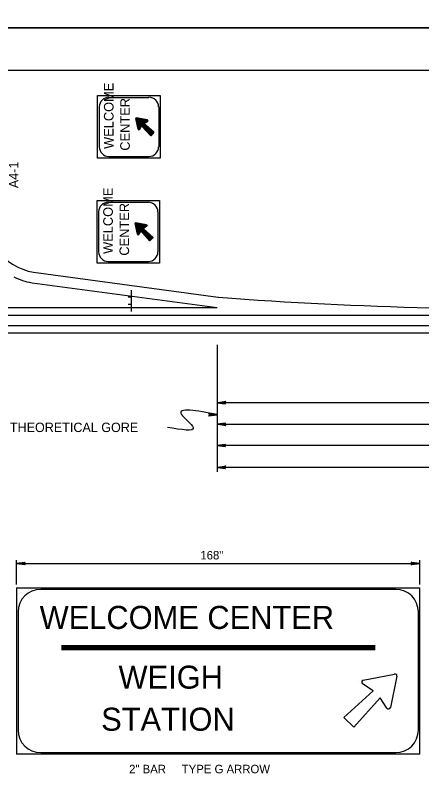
# Model space of a CAD drawing. Extents: x 2189973 to 2192941, y 2147557 to 2151454.
# Drawn here: x 2190705 to 2191176, y 2148636 to 2149520 of the extents above; entities that cross this region are included whole.
import ezdxf

# ---------------------------------------------------------------- set-up
doc = ezdxf.new("R2010")
doc.units = 0
doc.layers.add('Default', color=7, linetype='Continuous')
doc.layers.add('PLT-BNDY', color=7, linetype='Continuous')

# ---------------------------------------------------------------- blocks, each defined once
blk = doc.blocks.new('RARROW')
at = {"layer": 'Default'}
blk.add_lwpolyline([(-18.156, 2.28), (-17.479, 0.966), (0, 0), (-18.156, 2.28), (-19.086, 3.077), (0, 0), (-17.465, -0.864), (-18.103, -2.164), (0, 0), (-19.086, -3.033), (-18.103, -2.164)], dxfattribs=at)

msp = doc.modelspace()

# ---------------------------------------------------------------- linework, layer by layer
at = {"layer": 'Default'}
for p, q in [((2190104.48, 2149456.38), (2192683.21, 2149456.38)), ((2190813.55, 2149424.8), (2190859.89, 2149424.8)), ((2190844.31, 2149401.02), (2190844.31, 2149401.02)), ((2190844.72, 2149400.2), (2190847.59, 2149387.9)), ((2190857.84, 2149398.56), (2190845.54, 2149401.02)), ((2190854.15, 2149394.46), (2190858.66, 2149397.33)), ((2190859.89, 2149398.15), (2190859.89, 2149398.15)), ((2190848, 2149386.25), (2190848, 2149386.25)), ((2190848.82, 2149387.49), (2190851.28, 2149391.59)), ((2190851.28, 2149391.59), (2190851.28, 2149391.59)), ((2190851.28, 2149391.59), (2190861.94, 2149380.1)), ((2190854.15, 2149394.46), (2190854.15, 2149394.46)), ((2190865.63, 2149384.2), (2190854.15, 2149394.46)), ((2190861.94, 2149380.1), (2190865.63, 2149384.2)), ((2190873.02, 2149354.27), (2190800.43, 2149354.27)), ((2190859.89, 2149355.91), (2190813.55, 2149355.91)), ((2190812.73, 2149303), (2190859.48, 2149303)), ((2190843.49, 2149279.22), (2190843.49, 2149279.22)), ((2190843.9, 2149278.4), (2190846.77, 2149266.09)), ((2190857.02, 2149276.76), (2190844.72, 2149279.22)), ((2190853.33, 2149272.66), (2190857.43, 2149275.53)), ((2190853.33, 2149272.66), (2190853.33, 2149272.66)), ((2190864.81, 2149261.99), (2190853.33, 2149272.66)), ((2190859.07, 2149276.35), (2190859.07, 2149276.35)), ((2190847.18, 2149264.45), (2190847.18, 2149264.45)), ((2190848, 2149265.68), (2190850.46, 2149269.79)), ((2190850.46, 2149269.79), (2190850.46, 2149269.79)), ((2190850.46, 2149269.79), (2190861.12, 2149258.3)), ((2190861.12, 2149258.3), (2190864.81, 2149261.99)), ((2190872.19, 2149232.47), (2190800.02, 2149232.47)), ((2190859.48, 2149234.11), (2190812.73, 2149234.11)), ((2190726.2, 2149221.8), (2190940.27, 2149193.1)), ((2190724.56, 2149209.5), (2190724.56, 2149209.5)), ((2190724.56, 2149209.5), (2190939.04, 2149180.79)), ((2190839.8, 2149176.28), (2190839.8, 2149200.89)), ((2190839.8, 2149193.1), (2190835.7, 2149193.1)), ((2190839.8, 2149184.48), (2190835.7, 2149184.48)), ((2190155.33, 2149180.79), (2190939.04, 2149180.79)), ((2190939.04, 2149180.79), (2190939.04, 2149180.79)), ((2190939.04, 2149180.79), (2190939.04, 2149180.79)), ((2190114.32, 2149172.18), (2192679.93, 2149172.18)), ((2190114.32, 2149159.88), (2192679.93, 2149159.88)), ((2190114.32, 2149151.68), (2192679.93, 2149151.68)), ((2190939.04, 2149137.73), (2190939.04, 2148990.09)), ((2191714.55, 2149070.47), (2190939.04, 2149070.47)), ((2190939.04, 2149045.46), (2192091.43, 2149045.46)), ((2192264.5, 2149020.85), (2190939.04, 2149020.85)), ((2192437.97, 2148995.43), (2190939.04, 2148995.43)), ((2190706.54, 2148859.67), (2190706.54, 2148887.96)), ((2190706.54, 2148883.86), (2191174.05, 2148883.86)), ((2191174.05, 2148859.67), (2191174.05, 2148887.96)), ((2190706.54, 2148855.56), (2191174.05, 2148855.56)), ((2190706.54, 2148855.56), (2190706.54, 2148662.82)), ((2191146.17, 2148853.92), (2190734.42, 2148853.92)), ((2191174.05, 2148662.82), (2191174.05, 2148855.56)), ((2190708.18, 2148827.68), (2190708.18, 2148690.7)), ((2191172.41, 2148690.7), (2191172.41, 2148827.68)), ((2190758.62, 2148788.72), (2191122.38, 2148788.72)), ((2190758.62, 2148787.9), (2191122.38, 2148787.9)), ((2190758.62, 2148786.67), (2191122.38, 2148786.67)), ((2190758.62, 2148785.85), (2191122.38, 2148785.85)), ((2190758.62, 2148785.03), (2191122.38, 2148785.03)), ((2190758.62, 2148784.21), (2191122.38, 2148784.21)), ((2191108.44, 2148748.53), (2191144.53, 2148755.5)), ((2191147.4, 2148753.04), (2191140.02, 2148716.95)), ((2191147.4, 2148753.04), (2191140.02, 2148716.95)), ((2191147.81, 2148756.32), (2191147.81, 2148756.32)), ((2191103.52, 2148747.3), (2191103.52, 2148747.3)), ((2191119.92, 2148736.22), (2191107.62, 2148744.43)), ((2191119.92, 2148736.22), (2191107.62, 2148744.43)), ((2191085.88, 2148705.06), (2191119.92, 2148736.22)), ((2191085.88, 2148705.06), (2191119.92, 2148736.22)), ((2191119.92, 2148736.22), (2191119.92, 2148736.22)), ((2191128.12, 2148728.02), (2191097.36, 2148693.98)), ((2191128.12, 2148728.02), (2191097.36, 2148693.98)), ((2191124.02, 2148732.12), (2191124.02, 2148732.12)), ((2191135.91, 2148716.13), (2191128.12, 2148728.02)), ((2191128.12, 2148728.02), (2191128.12, 2148728.02)), ((2191139.2, 2148712.03), (2191139.2, 2148712.03)), ((2191097.36, 2148693.98), (2191085.88, 2148705.06)), ((2191097.36, 2148693.98), (2191085.88, 2148705.06)), ((2191085.88, 2148705.06), (2191085.88, 2148705.06)), ((2191097.36, 2148693.98), (2191097.36, 2148693.98)), ((2191174.05, 2148662.82), (2190706.54, 2148662.82)), ((2190734.42, 2148664.46), (2191146.17, 2148664.46))]:
    msp.add_line(p, q, dxfattribs=at)
for points in [[(2190800.43, 2149354.27), (2190800.43, 2149426.86), (2190807.81, 2149426.86), (2190818.88, 2149426.86), (2190826.67, 2149426.86), (2190837.75, 2149426.86), (2190844.31, 2149426.86), (2190866.04, 2149426.86), (2190873.02, 2149426.86), (2190873.02, 2149426.86), (2190873.02, 2149354.27), (2190873.02, 2149354.27)], [(2190802.48, 2149367.39), (2190802.48, 2149413.73)], [(2190871.37, 2149413.73), (2190871.37, 2149367.39)], [(2190861.94, 2149380.1), (2190851.28, 2149391.59), (2190848.82, 2149387.49), (2190848, 2149387.49), (2190847.59, 2149387.9), (2190844.72, 2149400.2), (2190845.13, 2149400.61), (2190845.54, 2149401.02), (2190857.84, 2149398.15), (2190858.66, 2149397.74), (2190857.84, 2149397.33), (2190853.74, 2149394.46), (2190865.63, 2149384.2), (2190861.94, 2149380.1), (2190851.28, 2149392), (2190848.41, 2149387.49), (2190848, 2149387.49), (2190848, 2149387.9), (2190845.13, 2149400.2), (2190845.13, 2149400.61), (2190845.54, 2149400.61), (2190857.84, 2149398.15), (2190857.84, 2149397.74), (2190857.84, 2149397.33), (2190853.74, 2149394.46), (2190865.22, 2149384.2), (2190861.94, 2149380.51), (2190851.28, 2149392), (2190848.41, 2149387.9), (2190848, 2149387.9), (2190848, 2149387.9), (2190845.13, 2149400.61), (2190857.84, 2149397.74), (2190853.33, 2149394.46), (2190864.81, 2149383.79), (2190861.94, 2149380.92), (2190851.28, 2149392.41), (2190848, 2149387.9), (2190845.54, 2149400.2)], [(2190848.41, 2149388.31), (2190845.54, 2149400.61), (2190857.84, 2149397.74), (2190852.92, 2149394.46), (2190864.81, 2149383.79), (2190861.94, 2149380.92), (2190851.28, 2149392.41), (2190848.41, 2149388.72), (2190846.36, 2149400.2), (2190857.43, 2149397.74), (2190852.92, 2149394.46), (2190864.4, 2149383.79), (2190861.94, 2149381.33), (2190851.28, 2149392.82), (2190848.41, 2149389.13), (2190846.36, 2149399.79), (2190856.61, 2149397.33), (2190852.51, 2149394.46), (2190863.99, 2149383.79), (2190861.94, 2149382.15), (2190851.28, 2149392.82), (2190848.82, 2149389.95), (2190846.77, 2149399.38), (2190855.79, 2149397.33), (2190852.1, 2149394.46), (2190863.58, 2149384.2), (2190861.94, 2149382.15), (2190851.28, 2149393.23), (2190848.82, 2149390.77), (2190847.18, 2149398.97), (2190855.38, 2149397.33), (2190851.69, 2149394.46), (2190863.17, 2149384.2), (2190861.94, 2149382.56), (2190851.28, 2149393.64), (2190848.82, 2149391.18), (2190847.59, 2149398.56), (2190854.56, 2149396.92), (2190851.69, 2149394.46), (2190862.76, 2149384.2), (2190862.76, 2149384.2), (2190861.94, 2149383.38), (2190850.87, 2149393.64), (2190849.23, 2149391.59), (2190848, 2149398.56), (2190854.15, 2149396.92), (2190851.28, 2149394.46), (2190862.35, 2149383.79), (2190861.94, 2149383.79), (2190851.28, 2149394.05), (2190849.23, 2149392.41), (2190848, 2149398.15), (2190853.33, 2149396.92), (2190851.28, 2149394.46), (2190862.35, 2149383.79), (2190861.94, 2149383.79), (2190851.28, 2149394.46), (2190849.64, 2149392.82), (2190848.41, 2149397.74), (2190853.33, 2149396.51), (2190849.64, 2149393.23), (2190848.82, 2149397.33), (2190852.51, 2149396.51), (2190849.64, 2149393.64), (2190849.23, 2149396.92), (2190852.1, 2149396.51), (2190849.64, 2149394.05), (2190849.23, 2149396.92), (2190851.69, 2149396.1), (2190850.05, 2149394.87), (2190849.64, 2149396.51), (2190850.87, 2149396.1), (2190850.05, 2149395.69), (2190850.05, 2149396.1), (2190850.46, 2149396.1)], [(2190800.02, 2149232.47), (2190800.02, 2149305.05), (2190806.99, 2149305.05), (2190818.06, 2149305.05), (2190825.85, 2149305.05), (2190836.93, 2149305.05), (2190843.49, 2149305.05), (2190865.22, 2149305.05), (2190872.19, 2149305.05), (2190872.19, 2149305.05), (2190872.19, 2149232.47), (2190872.19, 2149232.47)], [(2190801.66, 2149245.59), (2190801.66, 2149291.93)], [(2190870.14, 2149291.93), (2190870.14, 2149245.59)], [(2190861.12, 2149258.3), (2190850.46, 2149269.79), (2190848, 2149265.68), (2190847.59, 2149265.68), (2190846.77, 2149266.09), (2190843.9, 2149278.4), (2190844.31, 2149278.81), (2190844.72, 2149279.22), (2190857.02, 2149276.35), (2190857.43, 2149275.94), (2190857.43, 2149275.53), (2190853.33, 2149272.66), (2190864.81, 2149261.99), (2190861.12, 2149258.3), (2190850.46, 2149270.2), (2190847.59, 2149265.68), (2190847.59, 2149265.68), (2190847.18, 2149266.09), (2190844.31, 2149278.4), (2190844.31, 2149278.81), (2190844.72, 2149278.81), (2190857.02, 2149276.35), (2190857.43, 2149275.94), (2190857.02, 2149275.53), (2190852.92, 2149272.66), (2190864.4, 2149261.99), (2190861.12, 2149258.71), (2190850.46, 2149270.2), (2190847.59, 2149266.09), (2190847.18, 2149266.09), (2190847.18, 2149266.09), (2190844.31, 2149278.81), (2190857.02, 2149275.94), (2190852.92, 2149272.66), (2190864.4, 2149261.58), (2190861.12, 2149259.12), (2190850.46, 2149270.2), (2190847.59, 2149266.09), (2190844.72, 2149278.4)], [(2190847.59, 2149266.5), (2190844.72, 2149278.81), (2190857.02, 2149275.94), (2190852.51, 2149272.66), (2190863.99, 2149261.58), (2190861.12, 2149259.12), (2190850.46, 2149270.61), (2190847.59, 2149266.91), (2190845.13, 2149278.4), (2190856.61, 2149275.94), (2190852.1, 2149272.66), (2190863.99, 2149261.58), (2190861.12, 2149259.53), (2190850.46, 2149271.02), (2190848, 2149267.32), (2190845.13, 2149277.99), (2190855.79, 2149275.53), (2190851.69, 2149272.66), (2190863.58, 2149261.58), (2190861.12, 2149259.94), (2190850.46, 2149271.02), (2190848, 2149268.14), (2190845.54, 2149277.58), (2190854.97, 2149275.53), (2190851.28, 2149272.66), (2190862.76, 2149261.58), (2190861.12, 2149260.35), (2190850.46, 2149271.43), (2190848, 2149268.96), (2190846.36, 2149277.17), (2190854.56, 2149275.53), (2190851.28, 2149272.66), (2190862.35, 2149261.58), (2190861.12, 2149260.76), (2190850.46, 2149271.84), (2190848.41, 2149269.38), (2190846.77, 2149276.76), (2190853.74, 2149274.71), (2190850.87, 2149272.66), (2190861.94, 2149261.99), (2190861.94, 2149261.99), (2190861.12, 2149261.17), (2190850.46, 2149271.84), (2190848.41, 2149269.79), (2190847.18, 2149276.76), (2190853.33, 2149274.71), (2190850.87, 2149272.66), (2190861.94, 2149261.58), (2190861.12, 2149261.58), (2190850.46, 2149272.25), (2190848.41, 2149270.61), (2190847.18, 2149276.35), (2190852.92, 2149274.71), (2190850.46, 2149272.66), (2190861.53, 2149261.58), (2190861.12, 2149261.58), (2190850.46, 2149272.66), (2190848.82, 2149271.02), (2190847.59, 2149275.94), (2190852.51, 2149274.3), (2190848.82, 2149271.43), (2190848, 2149275.53), (2190852.1, 2149274.3), (2190848.82, 2149271.84), (2190848.41, 2149274.71), (2190851.69, 2149274.3), (2190849.23, 2149272.25), (2190848.82, 2149274.71), (2190850.87, 2149273.89), (2190849.23, 2149273.07), (2190848.82, 2149274.3), (2190850.46, 2149273.89), (2190849.64, 2149273.48), (2190849.23, 2149273.89), (2190849.64, 2149273.89)]]:
    msp.add_lwpolyline(points, dxfattribs=at)
for centre, radius, start, end in [((2190813.53, 2149413.76), 11.13, 90, 180), ((2190859.93, 2149413.76), 11.13, 0, 90), ((2190845.52, 2149400.33), 0.696, 78.09575, 191.90426), ((2190845.52, 2149400.33), 0.696, 78.09575, 191.90425), ((2190857.99, 2149397.71), 0.696, 302.69199, 78.09575), ((2190857.99, 2149397.71), 0.696, 302.69196, 78.09575), ((2190848.15, 2149387.87), 0.696, 191.90425, 327.30801), ((2190848.15, 2149387.87), 0.696, 191.90425, 327.30804), ((2190813.53, 2149367.37), 11.13, 180, 270), ((2190859.93, 2149367.37), 11.13, 270, 0), ((2190812.76, 2149291.88), 11.13, 90, 180), ((2190859.16, 2149291.88), 11.13, 0, 90), ((2190844.75, 2149278.45), 0.696, 78.09575, 191.90426), ((2190844.75, 2149278.45), 0.696, 78.09575, 191.90425), ((2190857.21, 2149275.83), 0.696, 302.69199, 78.09575), ((2190857.21, 2149275.83), 0.696, 302.69196, 78.09575), ((2190847.37, 2149265.99), 0.696, 191.90425, 327.30801), ((2190847.37, 2149265.99), 0.696, 191.90425, 327.30804), ((2190739.3, 2149291), 70.46, 217.68906, 259.20477), ((2190812.76, 2149245.49), 11.13, 180, 270), ((2190859.16, 2149245.49), 11.13, 270, 0), ((2190739.3, 2149291), 82.83, 244.19575, 259.20477), ((2191297.63, 2153881.5), 4702.16, 265.6447, 268.64351), ((2190734.42, 2148827.68), 26.25, 90, 180), ((2191146.17, 2148827.68), 26.25, 0, 90), ((2191145.34, 2148753.53), 2.25, 348.26016, 101.73982), ((2191145.34, 2148753.53), 2.25, 348.26016, 101.73982), ((2191108.84, 2148746.27), 2.21, 101.05641, 236.30993), ((2191137.83, 2148717.39), 2.25, 213.31623, 348.26016), ((2191137.83, 2148717.39), 2.25, 213.31623, 348.26016), ((2190734.42, 2148690.7), 26.25, 180, 270), ((2191146.17, 2148690.7), 26.25, 270, 0)]:
    msp.add_arc(centre, radius, start, end, dxfattribs=at)
msp.add_spline([(2190939.04, 2149056.94), (2190897.62, 2149056.94), (2190911.15, 2149041.77), (2190881.52, 2149041.77)], degree=3, dxfattribs=at)
at = {"layer": 'PLT-BNDY'}
for points in [[(2189973.25, 2151454.41), (2192732.43, 2151454.41), (2192732.43, 2149505.6), (2189973.25, 2149505.6)], [(2189973.25, 2149505.6), (2192732.43, 2149505.6), (2192732.43, 2147556.78), (2189973.25, 2147556.78)]]:
    msp.add_lwpolyline(points, close=True, dxfattribs=at)

# ---------------------------------------------------------------- block references
at = {"layer": 'Default', "xscale": 0.515679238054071, "yscale": 0.5369477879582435, "rotation": 180}
for p in [(2190939.04, 2149070.47), (2190939.04, 2149045.46), (2190939.04, 2149020.85), (2190939.04, 2148995.43), (2190706.53, 2148883.86)]:
    msp.add_blockref('RARROW', p, dxfattribs=at)
at = {"layer": 'Default', "xscale": 0.515679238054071, "yscale": 0.5369477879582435}
for p in [(2190938.87, 2149056.57), (2191174.05, 2148883.86)]:
    msp.add_blockref('RARROW', p, dxfattribs=at)

# ---------------------------------------------------------------- texts
at = {"layer": 'Default'}
for s, height, rotation, p in [('WELCOME', 11.129, 90, (2190818.88, 2149364.93)), ('CENTER', 11.129, 90, (2190837.75, 2149362.88)), ('A4-1', 10.886, 90, (2190708.56, 2149319.41)), ('WELCOME', 11.129, 90, (2190818.06, 2149243.13)), ('CENTER', 11.129, 90, (2190836.93, 2149241.08)), ('THEORETICAL GORE', 10.8833, 360, (2190698.72, 2149036.44)), ('WELCOME CENTER', 26.7175, 360, (2190733.19, 2148807.99)), ('WEIGH', 26.717, 360, (2190824.64, 2148738.68)), ('STATION', 26.717, 360, (2190804.55, 2148689.88))]:
    msp.add_text(s, height=height, rotation=rotation, dxfattribs=at).set_placement(p)
for s, height, p in [('168"', 9.842, (2190919.57, 2148888.61)), ('2" BAR     TYPE G ARROW', 9.8425, (2190836.98, 2148640.52))]:
    msp.add_text(s, height=height, dxfattribs=at).set_placement(p)

doc.saveas('drawing.dxf')
